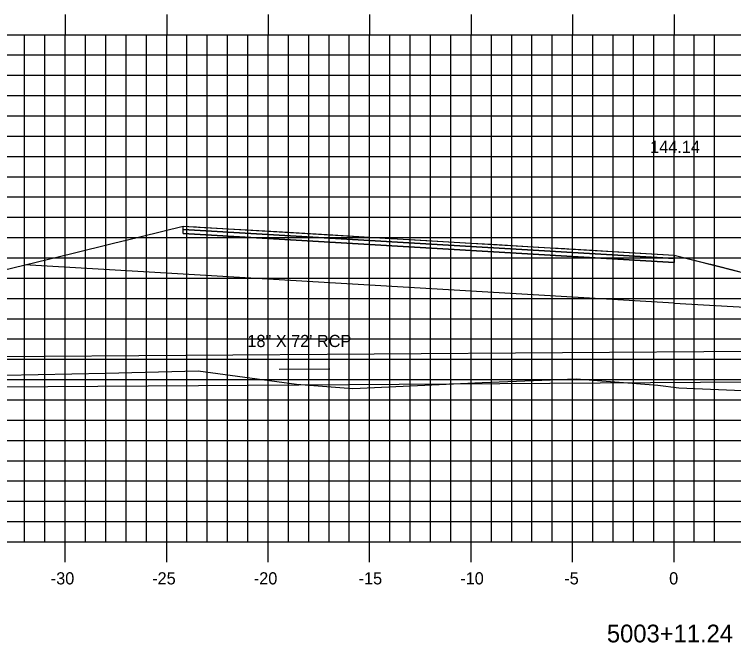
# Model space of a CAD drawing. Extents: x 851639 to 851810, y 365876 to 365986.
# Drawn here: x 851689.15 to 851724.59, y 365909.86 to 365940.84 of the extents above; entities that cross this region are included whole.
import ezdxf

# ---------------------------------------------------------------- set-up
doc = ezdxf.new("R2010")
doc.units = 0
for name, color, linetype in [('ANNOTATION', 7, 'Continuous'), ('D_Drainage_Culvert', 7, 'Continuous'), ('D_Drainage_Text', 7, 'Continuous'), ('D_Roadway_Centerline', 7, 'Continuous'), ('D_Roadway_Centerline_Text', 7, 'Continuous'), ('D_Roadway_Edge_TW', 7, 'Continuous'), ('D_Roadway_Pavement', 7, 'Continuous'), ('D_Roadway_SlopeLines', 7, 'Continuous'), ('D_Roadway_SubGrade', 7, 'Continuous'), ('H_V ANNOTATION', 7, 'Continuous'), ('MAJOR', 7, 'Continuous'), ('MINOR', 7, 'Continuous'), ('S_Roadway_Centerline', 7, 'Continuous')]:
    doc.layers.add(name, color=color, linetype=linetype)

msp = doc.modelspace()

# ---------------------------------------------------------------- linework, layer by layer
at = {"layer": 'ANNOTATION'}
for p, q in [((851697.464, 365928.026), (851689.647, 365928.485)), ((851721.655, 365926.605), (851733.788, 365925.893))]:
    msp.add_line(p, q, dxfattribs=at)
at = {"layer": 'D_Drainage_Culvert'}
for p, q in [((851741.273, 365924.315), (851669.281, 365923.829)), ((851704.693, 365923.342), (851702.2, 365923.321)), ((851741.289, 365922.815), (851669.291, 365922.329))]:
    msp.add_line(p, q, dxfattribs=at)
at = {"layer": 'D_Roadway_Centerline'}
msp.add_lwpolyline([(851687.569, 365927.977), (851689.622, 365928.478), (851692.048, 365929.071), (851693.971, 365929.54), (851694.443, 365929.655), (851694.656, 365929.707), (851695.394, 365929.888), (851697.464, 365930.392), (851697.98, 365930.362), (851698.041, 365930.359), (851698.116, 365930.354), (851698.118, 365930.354), (851698.229, 365930.348), (851702.077, 365930.124), (851704.838, 365929.963), (851705.86, 365929.902), (851706.386, 365929.871), (851707.418, 365929.811), (851708.611, 365929.742), (851709.48, 365929.69), (851711.363, 365929.579), (851712.945, 365929.487), (851714.962, 365929.367), (851715.84, 365929.316), (851715.952, 365929.309), (851716.267, 365929.291), (851716.678, 365929.266), (851716.801, 365929.259), (851717.341, 365929.228), (851719.454, 365929.102), (851719.736, 365929.086), (851721.655, 365928.972), (851722.326, 365928.802), (851722.513, 365928.754), (851723.303, 365928.554), (851723.446, 365928.518), (851724.853, 365928.161)], dxfattribs=at)
at = {"layer": 'D_Roadway_Edge_TW'}
msp.add_lwpolyline([(851697.464, 365930.392), (851721.655, 365928.972), (851721.655, 365928.805), (851697.464, 365930.226)], close=True, dxfattribs=at)
at = {"layer": 'D_Roadway_Pavement'}
msp.add_lwpolyline([(851697.464, 365930.226), (851721.655, 365928.805), (851721.655, 365928.605), (851697.464, 365930.026)], close=True, dxfattribs=at)
msp.add_lwpolyline([(851721.655, 365928.805), (851721.655, 365928.605)], dxfattribs=at)
msp.add_lwpolyline([(851721.655, 365928.805), (851721.655, 365928.605)], dxfattribs=at)
at = {"layer": 'D_Roadway_SlopeLines'}
msp.add_lwpolyline([(851721.655, 365928.972), (851731.754, 365926.409), (851736.518, 365925.198)], dxfattribs=at)
at = {"layer": 'D_Roadway_SubGrade'}
for points in [[(851697.464, 365930.026), (851721.655, 365928.605)], [(851721.655, 365926.605), (851697.464, 365928.026)]]:
    msp.add_lwpolyline(points, dxfattribs=at)
at = {"layer": 'MAJOR'}
for p, q in [((851691.655, 365940.835), (851691.655, 365939.833)), ((851696.655, 365940.835), (851696.655, 365939.833)), ((851701.655, 365940.835), (851701.655, 365939.833)), ((851706.655, 365940.835), (851706.655, 365939.833)), ((851711.655, 365940.835), (851711.655, 365939.833)), ((851716.655, 365940.835), (851716.655, 365939.833)), ((851721.655, 365940.835), (851721.655, 365939.833)), ((851651.655, 365939.833), (851791.655, 365939.833)), ((851651.655, 365939.833), (851791.655, 365939.833)), ((851691.655, 365914.833), (851691.655, 365939.833)), ((851696.655, 365914.833), (851696.655, 365939.833)), ((851701.655, 365914.833), (851701.655, 365939.833)), ((851706.655, 365914.833), (851706.655, 365939.833)), ((851711.655, 365914.833), (851711.655, 365939.833)), ((851716.655, 365914.833), (851716.655, 365939.833)), ((851721.655, 365914.833), (851721.655, 365939.833)), ((851651.655, 365934.833), (851791.655, 365934.833)), ((851651.655, 365929.833), (851791.655, 365929.833)), ((851651.655, 365924.833), (851791.655, 365924.833)), ((851651.655, 365919.833), (851791.655, 365919.833)), ((851651.655, 365914.833), (851791.655, 365914.833)), ((851651.655, 365914.833), (851791.655, 365914.833)), ((851691.655, 365913.831), (851691.655, 365914.833)), ((851696.655, 365913.831), (851696.655, 365914.833)), ((851701.655, 365913.831), (851701.655, 365914.833)), ((851706.655, 365913.831), (851706.655, 365914.833)), ((851711.655, 365913.831), (851711.655, 365914.833)), ((851716.655, 365913.831), (851716.655, 365914.833)), ((851721.655, 365913.831), (851721.655, 365914.833))]:
    msp.add_line(p, q, dxfattribs=at)
at = {"layer": 'MINOR'}
for p, q in [((851689.655, 365914.833), (851689.655, 365939.833)), ((851690.655, 365914.833), (851690.655, 365939.833)), ((851692.655, 365914.833), (851692.655, 365939.833)), ((851693.655, 365914.833), (851693.655, 365939.833)), ((851694.655, 365914.833), (851694.655, 365939.833)), ((851695.655, 365914.833), (851695.655, 365939.833)), ((851697.655, 365914.833), (851697.655, 365939.833)), ((851698.655, 365914.833), (851698.655, 365939.833)), ((851699.655, 365914.833), (851699.655, 365939.833)), ((851700.655, 365914.833), (851700.655, 365939.833)), ((851702.655, 365914.833), (851702.655, 365939.833)), ((851703.655, 365914.833), (851703.655, 365939.833)), ((851704.655, 365914.833), (851704.655, 365939.833)), ((851705.655, 365914.833), (851705.655, 365939.833)), ((851707.655, 365914.833), (851707.655, 365939.833)), ((851708.655, 365914.833), (851708.655, 365939.833)), ((851709.655, 365914.833), (851709.655, 365939.833)), ((851710.655, 365914.833), (851710.655, 365939.833)), ((851712.655, 365914.833), (851712.655, 365939.833)), ((851713.655, 365914.833), (851713.655, 365939.833)), ((851714.655, 365914.833), (851714.655, 365939.833)), ((851715.655, 365914.833), (851715.655, 365939.833)), ((851717.655, 365914.833), (851717.655, 365939.833)), ((851718.655, 365914.833), (851718.655, 365939.833)), ((851719.655, 365914.833), (851719.655, 365939.833)), ((851720.655, 365914.833), (851720.655, 365939.833)), ((851722.655, 365914.833), (851722.655, 365939.833)), ((851723.655, 365914.833), (851723.655, 365939.833)), ((851651.655, 365938.833), (851791.655, 365938.833)), ((851651.655, 365937.833), (851791.655, 365937.833)), ((851651.655, 365936.833), (851791.655, 365936.833)), ((851651.655, 365935.833), (851791.655, 365935.833)), ((851651.655, 365933.833), (851791.655, 365933.833)), ((851651.655, 365932.833), (851791.655, 365932.833)), ((851651.655, 365931.833), (851791.655, 365931.833)), ((851651.655, 365930.833), (851791.655, 365930.833)), ((851651.655, 365928.833), (851791.655, 365928.833)), ((851651.655, 365927.833), (851791.655, 365927.833)), ((851651.655, 365926.833), (851791.655, 365926.833)), ((851651.655, 365925.833), (851791.655, 365925.833)), ((851651.655, 365923.833), (851791.655, 365923.833)), ((851651.655, 365922.833), (851791.655, 365922.833)), ((851651.655, 365921.833), (851791.655, 365921.833)), ((851651.655, 365920.833), (851791.655, 365920.833)), ((851651.655, 365918.833), (851791.655, 365918.833)), ((851651.655, 365917.833), (851791.655, 365917.833)), ((851651.655, 365916.833), (851791.655, 365916.833)), ((851651.655, 365915.833), (851791.655, 365915.833))]:
    msp.add_line(p, q, dxfattribs=at)
at = {"layer": 'S_Roadway_Centerline'}
msp.add_lwpolyline([(851686.992, 365923.011), (851693.639, 365923.14), (851698.215, 365923.264), (851703.06, 365922.608), (851705.835, 365922.387), (851712.204, 365922.689), (851716.825, 365922.862), (851720.85, 365922.563), (851721.897, 365922.427), (851728.144, 365922.159), (851737.592, 365921.863), (851746.206, 365922.359), (851751.4, 365922.097)], dxfattribs=at)

# ---------------------------------------------------------------- texts
at = {"layer": 'D_Drainage_Text'}
msp.add_text('18" X 72\' RCP', height=0.6, dxfattribs=at).set_placement((851700.632, 365924.435))
at = {"layer": 'D_Roadway_Centerline_Text'}
msp.add_text('144.14', height=0.6, dxfattribs=at).set_placement((851720.478, 365934.004))
at = {"layer": 'H_V ANNOTATION'}
for s, height, p in [('-30', 0.6, (851690.943, 365912.733)), ('-25', 0.6, (851695.94, 365912.733)), ('-20', 0.6, (851700.948, 365912.733)), ('-15', 0.6, (851706.112, 365912.733)), ('-10', 0.6, (851711.12, 365912.733)), ('-5', 0.6, (851716.246, 365912.733)), ('0', 0.6, (851721.414, 365912.733)), ('5003+11.24', 0.875, (851718.347, 365909.876))]:
    msp.add_text(s, height=height, dxfattribs=at).set_placement(p)

doc.saveas('drawing.dxf')
